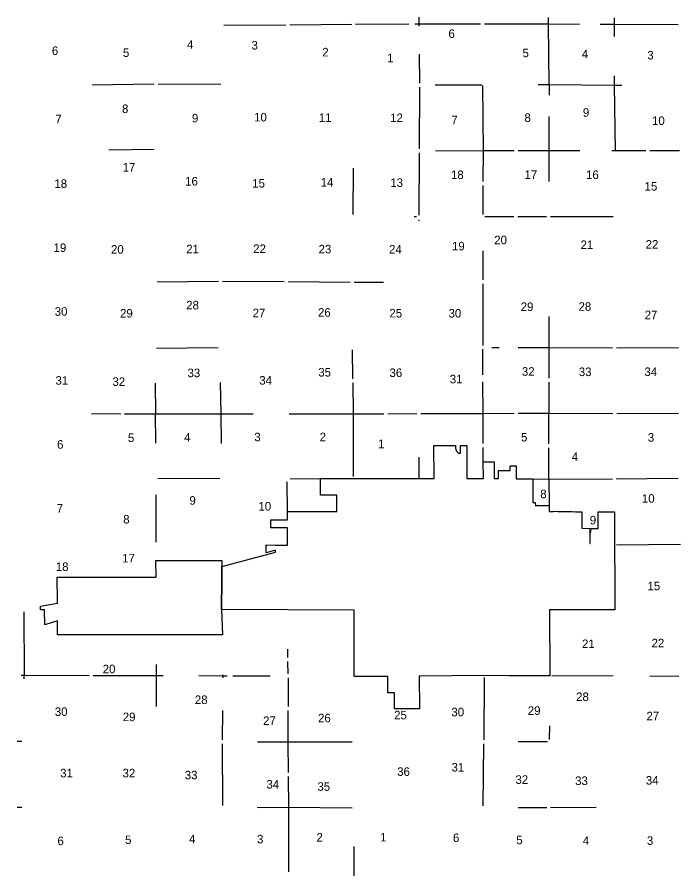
# Model space of a CAD drawing. Extents: x -2251611 to -2054719, y -2227156 to -2099355.
# Drawn here: x -2251608 to -2198431, y -2168284 to -2099355 of the extents above; entities that cross this region are included whole.
import ezdxf

# ---------------------------------------------------------------- set-up
doc = ezdxf.new("R2010")
doc.units = 0
for name, color, linetype in [('tdCoCorpBndry', 7, 'Continuous'), ('tdCoSectLinePart', 7, 'Continuous'), ('tdCoSectNmbr', 7, 'Continuous')]:
    doc.layers.add(name, color=color, linetype=linetype)

msp = doc.modelspace()

# ---------------------------------------------------------------- linework, layer by layer
at = {"layer": 'tdCoCorpBndry'}
for points in [[(-2219334, -2154887), (-2221334, -2154876), (-2221335, -2153599), (-2221854, -2153600), (-2221863, -2152276), (-2221917, -2152278), (-2223532, -2152275), (-2224566, -2152273), (-2224576, -2146948), (-2235202, -2146913), (-2235197, -2144487), (-2235194, -2143924), (-2235195, -2143861), (-2235195, -2143514), (-2235194, -2143450), (-2230874, -2142290), (-2230874, -2142199), (-2230874, -2142193), (-2230874, -2142139), (-2231635, -2142349), (-2231634, -2141727), (-2230874, -2141729), (-2229907, -2141732), (-2229908, -2141681), (-2229913, -2140352), (-2231245, -2140354), (-2231245, -2139702), (-2229916, -2139700), (-2229919, -2139043), (-2228409, -2139041), (-2225955, -2139038), (-2225958, -2137729), (-2227265, -2137733), (-2227268, -2136395), (-2224826, -2136388), (-2224635, -2136386), (-2221998, -2136391), (-2219575, -2136398), (-2219364, -2136386), (-2218152, -2136384), (-2218168, -2133740), (-2218083, -2133740), (-2218046, -2133740), (-2217847, -2133739), (-2217268, -2133739), (-2216830, -2133737), (-2216445, -2133735), (-2216445, -2133918), (-2216376, -2134167), (-2216205, -2134353), (-2216025, -2134353), (-2216028, -2133733), (-2215780, -2133731), (-2215529, -2133731), (-2215516, -2136379), (-2214199, -2136377), (-2214202, -2135050), (-2213333, -2135049), (-2213337, -2136394), (-2213165, -2136395), (-2212974, -2136397), (-2212992, -2135968), (-2212983, -2135748), (-2212043, -2135748), (-2212043, -2135374), (-2211564, -2135374), (-2211565, -2136403), (-2210239, -2136423), (-2210239, -2138307), (-2210027, -2138307), (-2210026, -2138586), (-2209961, -2138563), (-2209888, -2138555), (-2208923, -2138560), (-2208920, -2139027), (-2208614, -2139027), (-2208558, -2139026), (-2208280, -2139024), (-2208231, -2139025), (-2208112, -2139027), (-2207919, -2139030), (-2207740, -2139036), (-2207562, -2139043), (-2207390, -2139046), (-2207079, -2139050), (-2206791, -2139054), (-2206706, -2139056), (-2206379, -2139065), (-2206296, -2139065), (-2206296, -2140388), (-2205656, -2140390), (-2205655, -2141613), (-2205620, -2141610), (-2205620, -2140698), (-2205580, -2140698), (-2205580, -2140392), (-2204987, -2140392), (-2204985, -2139067), (-2203940, -2139064), (-2203685, -2139066), (-2203667, -2141507), (-2203664, -2141756), (-2203663, -2141912), (-2203663, -2141927), (-2203661, -2142261), (-2203661, -2142286), (-2203660, -2142309), (-2203651, -2144320), (-2203636, -2146926), (-2207540, -2146928), (-2208896, -2146928), (-2208862, -2152231), (-2211485, -2152236), (-2211856, -2152234), (-2212122, -2152232), (-2214128, -2152214), (-2219278, -2152257), (-2219341, -2152255)], [(-2248378, -2146407), (-2248379, -2146246), (-2248379, -2146234), (-2248389, -2144298), (-2245741, -2144310), (-2240461, -2144311), (-2240468, -2142973), (-2235188, -2142981), (-2235193, -2143355), (-2235194, -2143363), (-2235194, -2143450), (-2235195, -2143514), (-2235195, -2143861), (-2235194, -2143924), (-2235197, -2144487), (-2235202, -2146913), (-2235140, -2148945), (-2248362, -2148945), (-2248373, -2147821), (-2249397, -2148138), (-2249404, -2146938), (-2249430, -2146938), (-2249734, -2146937), (-2249738, -2146644)]]:
    msp.add_lwpolyline(points, close=True, dxfattribs=at)
at = {"layer": 'tdCoSectLinePart'}
for points in [[(-2219383, -2099355), (-2219383, -2099883)], [(-2208960, -2099896), (-2208960, -2099377)], [(-2203704, -2099403), (-2203703, -2099927)], [(-2235029, -2100003), (-2230050, -2099969)], [(-2229734, -2099967), (-2224763, -2099919)], [(-2224446, -2099917), (-2220179, -2099888)], [(-2219691, -2099885), (-2219383, -2099883)], [(-2219383, -2099883), (-2214434, -2099878)], [(-2219383, -2099883), (-2219380, -2100087)], [(-2214117, -2099878), (-2208960, -2099896)], [(-2208960, -2099896), (-2206486, -2099911)], [(-2208925, -2104749), (-2208960, -2099896)], [(-2204826, -2099921), (-2203703, -2099927)], [(-2203703, -2099927), (-2203704, -2100908)], [(-2203703, -2099927), (-2198564, -2099946)], [(-2219347, -2102314), (-2219313, -2104649)], [(-2203706, -2104062), (-2203707, -2104803)], [(-2245594, -2104785), (-2240605, -2104717)], [(-2240288, -2104715), (-2235260, -2104722)], [(-2219311, -2104966), (-2219337, -2109931)], [(-2218063, -2104790), (-2214310, -2104775)], [(-2214253, -2104833), (-2214225, -2110056)], [(-2209786, -2104753), (-2208925, -2104749)], [(-2208925, -2104749), (-2208928, -2105603)], [(-2208925, -2104749), (-2203707, -2104803)], [(-2203707, -2104803), (-2203091, -2104802)], [(-2203707, -2104803), (-2203625, -2110062)], [(-2208934, -2107318), (-2208944, -2110061)], [(-2244261, -2110017), (-2240627, -2109946)], [(-2219340, -2110246), (-2219379, -2115262)], [(-2218028, -2110081), (-2214225, -2110056)], [(-2214225, -2110056), (-2214227, -2112545)], [(-2214225, -2110056), (-2211731, -2110059)], [(-2211414, -2110059), (-2208944, -2110061)], [(-2208944, -2110061), (-2208955, -2112546)], [(-2208944, -2110061), (-2206450, -2110062)], [(-2203877, -2110062), (-2203625, -2110062)], [(-2203625, -2110062), (-2201166, -2110055)], [(-2203625, -2110087), (-2203625, -2110062)], [(-2200850, -2110054), (-2198468, -2110047)], [(-2224635, -2111487), (-2224664, -2115193)], [(-2214227, -2112862), (-2214228, -2115209)], [(-2219745, -2115360), (-2219559, -2115360)], [(-2214080, -2115355), (-2211739, -2115351)], [(-2211422, -2115350), (-2209126, -2115347)], [(-2208809, -2115346), (-2203790, -2115349)], [(-2219381, -2115626), (-2219382, -2115716)], [(-2214230, -2118118), (-2214232, -2120440)], [(-2240377, -2120591), (-2235445, -2120546)], [(-2235132, -2120546), (-2230181, -2120577)], [(-2229865, -2120579), (-2224879, -2120630)], [(-2224562, -2120631), (-2222220, -2120630)], [(-2214232, -2120754), (-2214247, -2125704)], [(-2208947, -2123392), (-2208930, -2125864)], [(-2240419, -2125921), (-2235486, -2125864)], [(-2224717, -2126068), (-2224687, -2128401)], [(-2214233, -2128062), (-2214247, -2126018)], [(-2213514, -2125863), (-2212919, -2125863)], [(-2211403, -2125864), (-2208930, -2125864)], [(-2208930, -2125864), (-2203827, -2125910)], [(-2208930, -2125864), (-2208930, -2128347)], [(-2203510, -2125911), (-2198548, -2125885)], [(-2240537, -2128724), (-2240504, -2131206)], [(-2235240, -2131190), (-2235282, -2128694)], [(-2224683, -2128718), (-2224651, -2131188)], [(-2214213, -2131163), (-2214230, -2128618)], [(-2208930, -2128664), (-2208931, -2131147)], [(-2245633, -2131183), (-2243303, -2131193)], [(-2242986, -2131195), (-2240504, -2131206)], [(-2240504, -2131206), (-2235240, -2131190)], [(-2240490, -2133565), (-2240504, -2131206)], [(-2235240, -2131190), (-2232667, -2131190)], [(-2235217, -2133569), (-2235240, -2131190)], [(-2229783, -2131189), (-2224651, -2131188)], [(-2224651, -2131188), (-2222174, -2131185)], [(-2224651, -2131188), (-2224637, -2136229)], [(-2221857, -2131185), (-2219539, -2131182)], [(-2219221, -2131181), (-2214213, -2131163)], [(-2214213, -2131163), (-2211731, -2131156)], [(-2214208, -2133571), (-2214213, -2131163)], [(-2211414, -2131155), (-2208931, -2131147)], [(-2208937, -2133608), (-2208931, -2131147)], [(-2208931, -2131147), (-2203813, -2131171)], [(-2203496, -2131172), (-2198545, -2131151)], [(-2214204, -2135050), (-2214207, -2133887)], [(-2208944, -2136437), (-2208938, -2133924)], [(-2219370, -2134669), (-2219366, -2136386)], [(-2240315, -2136378), (-2235348, -2136370)], [(-2229920, -2139043), (-2229931, -2136660)], [(-2229707, -2136404), (-2227270, -2136395), (-2225333, -2136388)], [(-2221842, -2136386), (-2219740, -2136386)], [(-2219417, -2136386), (-2219366, -2136386)], [(-2213339, -2136387), (-2212976, -2136391)], [(-2210241, -2136423), (-2208944, -2136437)], [(-2208944, -2136437), (-2203847, -2136408)], [(-2208944, -2136437), (-2208926, -2138560)], [(-2203530, -2136406), (-2198561, -2136370)], [(-2240472, -2137702), (-2240470, -2141505)], [(-2203509, -2141710), (-2198389, -2141669)], [(-2251072, -2147097), (-2251039, -2152179)], [(-2229890, -2150769), (-2229899, -2150097)], [(-2229872, -2152079), (-2229886, -2151084)], [(-2240424, -2152207), (-2240430, -2151324)], [(-2251285, -2152181), (-2251039, -2152179)], [(-2251042, -2152480), (-2251039, -2152179)], [(-2251039, -2152179), (-2245828, -2152195)], [(-2245511, -2152196), (-2240424, -2152207)], [(-2240424, -2152207), (-2239895, -2152209)], [(-2240416, -2154701), (-2240424, -2152207)], [(-2237040, -2152216), (-2235111, -2152221)], [(-2235111, -2152221), (-2235113, -2152383)], [(-2235111, -2152221), (-2235112, -2152150)], [(-2235111, -2152221), (-2234756, -2152222)], [(-2234293, -2152224), (-2231308, -2152233)], [(-2229871, -2152394), (-2229874, -2154688)], [(-2214131, -2152372), (-2214159, -2157360)], [(-2208706, -2152230), (-2203772, -2152198)], [(-2200841, -2152222), (-2198511, -2152244)], [(-2235141, -2155022), (-2235166, -2157360)], [(-2229875, -2155005), (-2229879, -2157521)], [(-2208895, -2156246), (-2208903, -2157350)], [(-2251607, -2157483), (-2251239, -2157482)], [(-2235166, -2157676), (-2235120, -2162642)], [(-2232334, -2157520), (-2229879, -2157521)], [(-2229879, -2157521), (-2229862, -2159992)], [(-2229879, -2157521), (-2224729, -2157537)], [(-2214208, -2162655), (-2214161, -2157676)], [(-2211395, -2157513), (-2209063, -2157509)], [(-2229860, -2160309), (-2229843, -2162782)], [(-2251608, -2162761), (-2251236, -2162761)], [(-2232355, -2162790), (-2229843, -2162782)], [(-2229843, -2162782), (-2229845, -2167969)], [(-2229843, -2162782), (-2224735, -2162821)], [(-2211412, -2162805), (-2209116, -2162799)], [(-2208800, -2162797), (-2205156, -2162777)], [(-2224579, -2165926), (-2224581, -2168284)]]:
    msp.add_lwpolyline(points, dxfattribs=at)

# ---------------------------------------------------------------- texts
at = {"layer": 'tdCoSectNmbr'}
for s, height, rotation, p in [('6', 686, 0.00561, (-2217000, -2101019)), ('4', 686, 0.00256, (-2237969, -2101888)), ('3', 686, 0.00331, (-2232804, -2101951)), ('6', 686, 0.00101, (-2248826, -2102391)), ('5', 686, 0.00181, (-2243119, -2102546)), ('2', 686, 0.00413, (-2227124, -2102508)), ('1', 686, 0.00488, (-2221917, -2102971)), ('5', 686, 0.00647, (-2211051, -2102571)), ('4', 686, 0.00716, (-2206295, -2102647)), ('3', 686, 0.00793, (-2201042, -2102749)), ('8', 686, 0.00179, (-2243195, -2107050)), ('9', 686, 0.0026, (-2237587, -2107804)), ('10', 686.4, 0.00334, (-2232593, -2107728)), ('11', 686.4, 0.00408, (-2227397, -2107759)), ('12', 686.4, 0.00492, (-2221679, -2107775)), ('8', 686, 0.00648, (-2210902, -2107766)), ('9', 686, 0.00716, (-2206213, -2107352)), ('7', 686, 0.00101, (-2248549, -2107876)), ('7', 686, 0.00563, (-2216766, -2107956)), ('10', 686.4, 0.00798, (-2200663, -2108010)), ('17', 686.4, 0.00179, (-2243146, -2111748)), ('18', 686.4, 0.00563, (-2216797, -2112351)), ('17', 686.4, 0.00648, (-2210899, -2112347)), ('16', 686.4, 0.0072, (-2205960, -2112348)), ('18', 686.4, 0.001, (-2248623, -2113061)), ('16', 686.4, 0.00252, (-2238129, -2112868)), ('15', 686.4, 0.0033, (-2232743, -2113037)), ('14', 686.4, 0.0041, (-2227251, -2112951)), ('13', 686.4, 0.00491, (-2221665, -2112980)), ('15', 686.4, 0.00788, (-2201257, -2113278)), ('19', 686.4, 0.00098, (-2248689, -2118201)), ('19', 686.4, 0.00562, (-2216717, -2118078)), ('20', 686.4, 0.00613, (-2213323, -2117585)), ('21', 686.4, 0.00711, (-2206396, -2117967)), ('22', 686.4, 0.00788, (-2201175, -2117937)), ('20', 686.4, 0.00176, (-2244082, -2118338)), ('21', 686.4, 0.00252, (-2238041, -2118310)), ('22', 686.4, 0.0033, (-2232669, -2118288)), ('23', 686.4, 0.00407, (-2227423, -2118318)), ('24', 686.4, 0.00489, (-2221767, -2118327)), ('28', 686.4, 0.00253, (-2238046, -2122815)), ('29', 686.4, 0.00648, (-2211204, -2122943)), ('28', 686.4, 0.00708, (-2206558, -2122926)), ('30', 686.4, 0.00098, (-2248599, -2123325)), ('29', 686.4, 0.00174, (-2243354, -2123469)), ('27', 686.4, 0.00326, (-2232711, -2123441)), ('26', 686.4, 0.00405, (-2227468, -2123399)), ('25', 686.4, 0.00489, (-2221739, -2123462)), ('30', 686.4, 0.00556, (-2216992, -2123470)), ('27', 686.4, 0.00791, (-2201251, -2123602)), ('33', 686.4, 0.00253, (-2237939, -2128255)), ('35', 686.4, 0.00405, (-2227444, -2128203)), ('36', 686.4, 0.00488, (-2221729, -2128241)), ('32', 686.4, 0.00642, (-2211107, -2128141)), ('33', 686.4, 0.00708, (-2206536, -2128167)), ('34', 686.4, 0.00785, (-2201272, -2128163)), ('31', 686.4, 0.00094, (-2248532, -2128861)), ('32', 686.4, 0.00164, (-2243965, -2128954)), ('34', 686.4, 0.00336, (-2232178, -2128854)), ('31', 686.4, 0.00557, (-2216891, -2128752)), ('6', 686, 0.00093, (-2248407, -2133996)), ('5', 686, 0.0018, (-2242718, -2133462)), ('4', 686, 0.00245, (-2238208, -2133422)), ('3', 686, 0.00327, (-2232579, -2133401)), ('2', 686, 0.00403, (-2227334, -2133393)), ('1', 686, 0.0047, (-2222641, -2133954)), ('5', 686, 0.00639, (-2211173, -2133415)), ('3', 686, 0.00784, (-2201001, -2133431)), ('4', 686, 0.00689, (-2207104, -2134978)), ('8', 686, 0.00659, (-2209633, -2137969)), ('9', 686, 0.0025, (-2237785, -2138493)), ('10', 686.4, 0.00783, (-2201473, -2138335)), ('7', 686, 0.00095, (-2248437, -2139130)), ('10', 686.4, 0.00321, (-2232252, -2138961)), ('8', 686, 0.00168, (-2243098, -2140004)), ('9', 686, 0.00706, (-2205655, -2140074)), ('17', 686.4, 0.00171, (-2243184, -2143127)), ('18', 686.4, 0.001, (-2248509, -2143814)), ('15', 686.4, 0.00788, (-2201027, -2145359)), ('21', 686.4, 0.00709, (-2206284, -2150002)), ('22', 686.4, 0.00787, (-2200698, -2149937)), ('20', 686.4, 0.00169, (-2244744, -2152022)), ('28', 686.4, 0.00255, (-2237350, -2154491)), ('28', 686.4, 0.00642, (-2206756, -2154252)), ('29', 686.4, 0.00642, (-2210632, -2155363)), ('30', 686.4, 0.00088, (-2248588, -2155450)), ('29', 686.4, 0.00171, (-2243135, -2155868)), ('26', 686.4, 0.00394, (-2227465, -2155962)), ('25', 686.4, 0.00486, (-2221360, -2155726)), ('30', 686.4, 0.00549, (-2216763, -2155479)), ('27', 686.4, 0.00642, (-2201105, -2155798)), ('27', 686.4, 0.00334, (-2231872, -2156172)), ('31', 686.4, 0.00548, (-2216748, -2159912)), ('31', 686.4, 0.00088, (-2248155, -2160379)), ('32', 686.4, 0.00165, (-2243150, -2160381)), ('33', 686.4, 0.00244, (-2238163, -2160537)), ('36', 686.4, 0.00489, (-2221114, -2160264)), ('32', 686.4, 0.00624, (-2211623, -2160901)), ('34', 686.4, 0.00336, (-2231606, -2161280)), ('35', 686.4, 0.00399, (-2227517, -2161459)), ('33', 686.4, 0.00701, (-2206831, -2160995)), ('34', 686.4, 0.00778, (-2201158, -2160961)), ('5', 686, 0.00169, (-2242951, -2165734)), ('4', 686, 0.00243, (-2237811, -2165666)), ('3', 686, 0.0032, (-2232360, -2165681)), ('2', 686, 0.00392, (-2227589, -2165535)), ('1', 686, 0.00465, (-2222475, -2165527)), ('6', 686, 0.0055, (-2216640, -2165569)), ('5', 686, 0.0062, (-2211553, -2165749)), ('6', 686, 0.00089, (-2248375, -2165822)), ('4', 686, 0.00699, (-2206213, -2165788)), ('3', 686, 0.00776, (-2201073, -2165799))]:
    msp.add_text(s, height=height, rotation=rotation, dxfattribs=at).set_placement(p)

doc.saveas('drawing.dxf')
